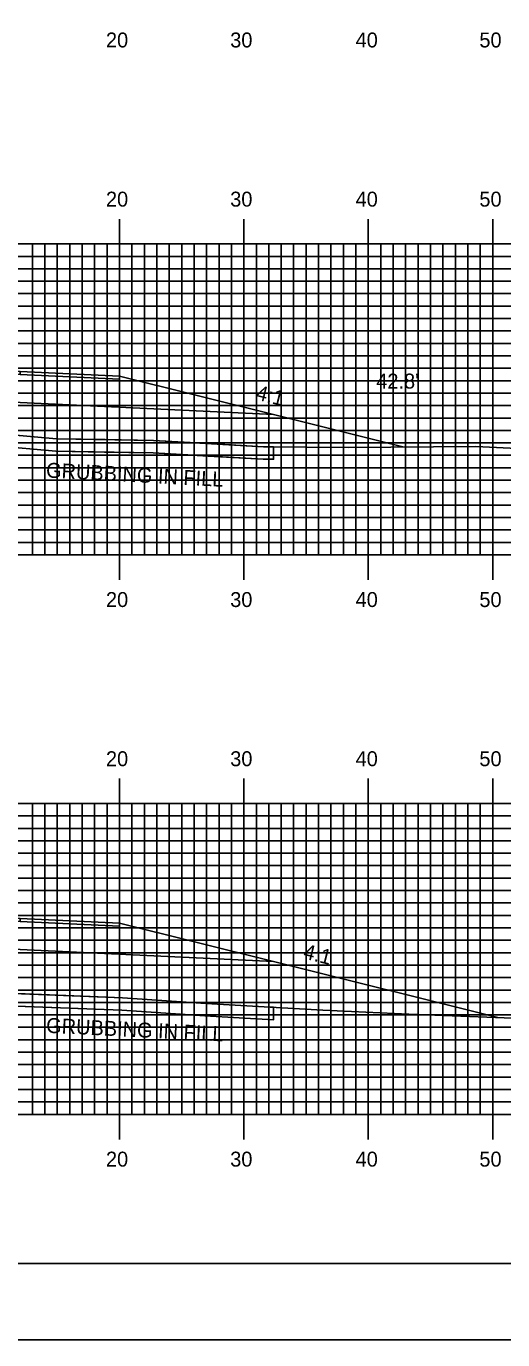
# Model space of a CAD drawing. Extents: x 1814128 to 1814471, y 442591 to 442811.
# Drawn here: x 1814306.5 to 1814344.8, y 442590.5 to 442696.2 of the extents above; entities that cross this region are included whole.
import ezdxf

# ---------------------------------------------------------------- set-up
doc = ezdxf.new("R2010")
doc.units = 0
for name, color, linetype in [('ANNOTATION', 7, 'Continuous'), ('BORDER', 7, 'Continuous'), ('D_Roadway_Centerline', 7, 'Continuous'), ('D_Roadway_Edge_Shoulder', 7, 'Continuous'), ('D_Roadway_SlopeLines', 7, 'Continuous'), ('D_Roadway_SubGrade', 7, 'Continuous'), ('D_Text_Standard', 7, 'Continuous'), ('GRUBBING IN FILL', 7, 'Continuous'), ('H_V ANNOTATION', 7, 'Continuous'), ('MAJOR', 7, 'Continuous'), ('MINOR', 7, 'Continuous'), ('PLOT BOUNDARY', 7, 'Continuous'), ('S_Roadway_Centerline', 7, 'Continuous')]:
    doc.layers.add(name, color=color, linetype=linetype)

msp = doc.modelspace()

# ---------------------------------------------------------------- linework, layer by layer
at = {"layer": 'BORDER'}
msp.add_lwpolyline([(1814144.39, 442596.67), (1814464.39, 442596.67), (1814464.39, 442806.67), (1814144.39, 442806.67)], close=True, dxfattribs=at)
at = {"layer": 'D_Roadway_Centerline'}
for points in [[(1814257.01, 442665.16), (1814261.99, 442666.41), (1814263.12, 442666.69), (1814273.99, 442669.41), (1814281.99, 442669.57), (1814293.99, 442668.99), (1814305.99, 442668.42), (1814313.99, 442668.03), (1814326.37, 442664.94), (1814336.78, 442662.34)], [(1814250.99, 442620.3), (1814259.24, 442622.37), (1814260.37, 442622.65), (1814271.24, 442625.37), (1814281.99, 442625.58), (1814293.99, 442625.01), (1814305.99, 442624.43), (1814313.99, 442624.05), (1814326.37, 442620.95), (1814344.4, 442616.45)]]:
    msp.add_lwpolyline(points, dxfattribs=at)
at = {"layer": 'D_Roadway_Edge_Shoulder'}
for points in [[(1814305.99, 442668.42), (1814313.99, 442668.03), (1814313.99, 442667.78), (1814305.99, 442668.17)], [(1814305.99, 442624.43), (1814313.99, 442624.05), (1814313.99, 442623.8), (1814305.99, 442624.18)]]:
    msp.add_lwpolyline(points, close=True, dxfattribs=at)
at = {"layer": 'D_Roadway_SlopeLines'}
for points in [[(1814313.99, 442668.03), (1814326.37, 442664.94), (1814336.78, 442662.34)], [(1814313.99, 442624.05), (1814326.37, 442620.95), (1814344.4, 442616.45)]]:
    msp.add_lwpolyline(points, dxfattribs=at)
at = {"layer": 'D_Roadway_SubGrade'}
for points in [[(1814281.99, 442667.07), (1814263.12, 442666.69), (1814273.99, 442669.41), (1814273.99, 442669.16), (1814281.99, 442669.32), (1814293.99, 442668.74), (1814305.99, 442668.17), (1814313.99, 442667.78), (1814313.99, 442668.03), (1814326.37, 442664.94), (1814305.99, 442665.92), (1814293.99, 442666.49)], [(1814281.99, 442623.08), (1814260.37, 442622.65), (1814271.24, 442625.37), (1814271.24, 442625.12), (1814281.99, 442625.33), (1814293.99, 442624.76), (1814305.99, 442624.18), (1814313.99, 442623.8), (1814313.99, 442624.05), (1814326.37, 442620.95), (1814305.99, 442621.93), (1814293.99, 442622.51)]]:
    msp.add_lwpolyline(points, close=True, dxfattribs=at)
at = {"layer": 'GRUBBING IN FILL'}
for p, q in [((1814326.37, 442662.35), (1814326.37, 442661.35)), ((1814326.37, 442662.35), (1814326.37, 442661.35)), ((1814326.37, 442617.28), (1814326.37, 442616.28)), ((1814326.37, 442617.28), (1814326.37, 442616.28))]:
    msp.add_line(p, q, dxfattribs=at)
for points in [[(1814263.12, 442663.84), (1814275.17, 442663.27), (1814283.53, 442662.9), (1814291.88, 442663.36), (1814299.24, 442662.87), (1814308.87, 442662), (1814316.69, 442661.86), (1814325.53, 442661.36), (1814326.37, 442661.35)], [(1814263.12, 442663.84), (1814275.17, 442663.27), (1814283.53, 442662.9), (1814291.88, 442663.36), (1814299.24, 442662.87), (1814308.87, 442662), (1814316.69, 442661.86), (1814325.53, 442661.36), (1814326.37, 442661.35)], [(1814260.37, 442618.87), (1814265.26, 442618.76), (1814273.92, 442618.48), (1814282.8, 442618.22), (1814297.25, 442617.7), (1814314.18, 442617.05), (1814320.86, 442616.6), (1814326.37, 442616.28)], [(1814260.37, 442618.87), (1814265.26, 442618.76), (1814273.92, 442618.48), (1814282.8, 442618.22), (1814297.25, 442617.7), (1814314.18, 442617.05), (1814320.86, 442616.6), (1814326.37, 442616.28)]]:
    msp.add_lwpolyline(points, dxfattribs=at)
for points in [[(1814293.99, 442664.22), (1814295.6, 442664.12), (1814299.32, 442663.86), (1814304.12, 442663.43), (1814308.93, 442663), (1814312.83, 442662.93), (1814316.73, 442662.86), (1814321.15, 442662.61), (1814325.57, 442662.36), (1814326.37, 442662.35), (1814326.37, 442661.35), (1814325.53, 442661.36), (1814321.11, 442661.61), (1814316.69, 442661.86), (1814312.78, 442661.93), (1814308.87, 442662), (1814304.05, 442662.43), (1814299.24, 442662.87), (1814293.99, 442663.22)], [(1814293.99, 442664.22), (1814295.6, 442664.12), (1814299.32, 442663.86), (1814304.12, 442663.43), (1814308.93, 442663), (1814312.83, 442662.93), (1814316.73, 442662.86), (1814321.15, 442662.61), (1814325.57, 442662.36), (1814326.37, 442662.35), (1814326.37, 442661.35), (1814325.53, 442661.36), (1814321.11, 442661.61), (1814316.69, 442661.86), (1814312.78, 442661.93), (1814308.87, 442662), (1814304.05, 442662.43), (1814299.24, 442662.87), (1814293.99, 442663.22)], [(1814293.99, 442618.82), (1814297.29, 442618.7), (1814305.76, 442618.38), (1814314.23, 442618.05), (1814320.92, 442617.59), (1814325.63, 442617.32), (1814326.37, 442617.28), (1814326.37, 442616.28), (1814323.61, 442616.44), (1814320.86, 442616.6), (1814314.18, 442617.05), (1814305.72, 442617.38), (1814297.25, 442617.7), (1814293.99, 442617.82)], [(1814293.99, 442618.82), (1814297.29, 442618.7), (1814305.76, 442618.38), (1814314.23, 442618.05), (1814320.92, 442617.59), (1814325.63, 442617.32), (1814326.37, 442617.28), (1814326.37, 442616.28), (1814323.61, 442616.44), (1814320.86, 442616.6), (1814314.18, 442617.05), (1814305.72, 442617.38), (1814297.25, 442617.7), (1814293.99, 442617.82)]]:
    msp.add_lwpolyline(points, close=True, dxfattribs=at)
at = {"layer": 'MAJOR'}
for p, q in [((1814313.99, 442680.67), (1814313.99, 442678.67)), ((1814323.99, 442680.67), (1814323.99, 442678.67)), ((1814333.99, 442680.67), (1814333.99, 442678.67)), ((1814343.99, 442680.67), (1814343.99, 442678.67)), ((1814153.99, 442678.67), (1814433.99, 442678.67)), ((1814153.99, 442678.67), (1814433.99, 442678.67)), ((1814313.99, 442653.67), (1814313.99, 442678.67)), ((1814323.99, 442653.67), (1814323.99, 442678.67)), ((1814333.99, 442653.67), (1814333.99, 442678.67)), ((1814343.99, 442653.67), (1814343.99, 442678.67)), ((1814153.99, 442673.67), (1814433.99, 442673.67)), ((1814153.99, 442668.67), (1814433.99, 442668.67)), ((1814153.99, 442663.67), (1814433.99, 442663.67)), ((1814153.99, 442658.67), (1814433.99, 442658.67)), ((1814153.99, 442653.67), (1814433.99, 442653.67)), ((1814153.99, 442653.67), (1814433.99, 442653.67)), ((1814313.99, 442651.66), (1814313.99, 442653.67)), ((1814323.99, 442651.66), (1814323.99, 442653.67)), ((1814333.99, 442651.66), (1814333.99, 442653.67)), ((1814343.99, 442651.66), (1814343.99, 442653.67)), ((1814313.99, 442635.67), (1814313.99, 442633.67)), ((1814323.99, 442635.67), (1814323.99, 442633.67)), ((1814333.99, 442635.67), (1814333.99, 442633.67)), ((1814343.99, 442635.67), (1814343.99, 442633.67)), ((1814153.99, 442633.67), (1814433.99, 442633.67)), ((1814153.99, 442633.67), (1814433.99, 442633.67)), ((1814313.99, 442608.67), (1814313.99, 442633.67)), ((1814323.99, 442608.67), (1814323.99, 442633.67)), ((1814333.99, 442608.67), (1814333.99, 442633.67)), ((1814343.99, 442608.67), (1814343.99, 442633.67)), ((1814153.99, 442628.67), (1814433.99, 442628.67)), ((1814153.99, 442623.67), (1814433.99, 442623.67)), ((1814153.99, 442618.67), (1814433.99, 442618.67)), ((1814153.99, 442613.67), (1814433.99, 442613.67)), ((1814153.99, 442608.67), (1814433.99, 442608.67)), ((1814153.99, 442608.67), (1814433.99, 442608.67)), ((1814313.99, 442606.66), (1814313.99, 442608.67)), ((1814323.99, 442606.66), (1814323.99, 442608.67)), ((1814333.99, 442606.66), (1814333.99, 442608.67)), ((1814343.99, 442606.66), (1814343.99, 442608.67))]:
    msp.add_line(p, q, dxfattribs=at)
at = {"layer": 'MINOR'}
for p, q in [((1814306.99, 442653.67), (1814306.99, 442678.67)), ((1814307.99, 442653.67), (1814307.99, 442678.67)), ((1814308.99, 442653.67), (1814308.99, 442678.67)), ((1814309.99, 442653.67), (1814309.99, 442678.67)), ((1814310.99, 442653.67), (1814310.99, 442678.67)), ((1814311.99, 442653.67), (1814311.99, 442678.67)), ((1814312.99, 442653.67), (1814312.99, 442678.67)), ((1814314.99, 442653.67), (1814314.99, 442678.67)), ((1814315.99, 442653.67), (1814315.99, 442678.67)), ((1814316.99, 442653.67), (1814316.99, 442678.67)), ((1814317.99, 442653.67), (1814317.99, 442678.67)), ((1814318.99, 442653.67), (1814318.99, 442678.67)), ((1814319.99, 442653.67), (1814319.99, 442678.67)), ((1814320.99, 442653.67), (1814320.99, 442678.67)), ((1814321.99, 442653.67), (1814321.99, 442678.67)), ((1814322.99, 442653.67), (1814322.99, 442678.67)), ((1814324.99, 442653.67), (1814324.99, 442678.67)), ((1814325.99, 442653.67), (1814325.99, 442678.67)), ((1814326.99, 442653.67), (1814326.99, 442678.67)), ((1814327.99, 442653.67), (1814327.99, 442678.67)), ((1814328.99, 442653.67), (1814328.99, 442678.67)), ((1814329.99, 442653.67), (1814329.99, 442678.67)), ((1814330.99, 442653.67), (1814330.99, 442678.67)), ((1814331.99, 442653.67), (1814331.99, 442678.67)), ((1814332.99, 442653.67), (1814332.99, 442678.67)), ((1814334.99, 442653.67), (1814334.99, 442678.67)), ((1814335.99, 442653.67), (1814335.99, 442678.67)), ((1814336.99, 442653.67), (1814336.99, 442678.67)), ((1814337.99, 442653.67), (1814337.99, 442678.67)), ((1814338.99, 442653.67), (1814338.99, 442678.67)), ((1814339.99, 442653.67), (1814339.99, 442678.67)), ((1814340.99, 442653.67), (1814340.99, 442678.67)), ((1814341.99, 442653.67), (1814341.99, 442678.67)), ((1814342.99, 442653.67), (1814342.99, 442678.67)), ((1814153.99, 442677.67), (1814433.99, 442677.67)), ((1814153.99, 442676.67), (1814433.99, 442676.67)), ((1814153.99, 442675.67), (1814433.99, 442675.67)), ((1814153.99, 442674.67), (1814433.99, 442674.67)), ((1814153.99, 442672.67), (1814433.99, 442672.67)), ((1814153.99, 442671.67), (1814433.99, 442671.67)), ((1814153.99, 442670.67), (1814433.99, 442670.67)), ((1814153.99, 442669.67), (1814433.99, 442669.67)), ((1814153.99, 442667.67), (1814433.99, 442667.67)), ((1814153.99, 442666.67), (1814433.99, 442666.67)), ((1814153.99, 442665.67), (1814433.99, 442665.67)), ((1814153.99, 442664.67), (1814433.99, 442664.67)), ((1814153.99, 442662.67), (1814433.99, 442662.67)), ((1814153.99, 442661.67), (1814433.99, 442661.67)), ((1814153.99, 442660.67), (1814433.99, 442660.67)), ((1814153.99, 442659.67), (1814433.99, 442659.67)), ((1814153.99, 442657.67), (1814433.99, 442657.67)), ((1814153.99, 442656.67), (1814433.99, 442656.67)), ((1814153.99, 442655.67), (1814433.99, 442655.67)), ((1814153.99, 442654.67), (1814433.99, 442654.67)), ((1814306.99, 442608.67), (1814306.99, 442633.67)), ((1814307.99, 442608.67), (1814307.99, 442633.67)), ((1814308.99, 442608.67), (1814308.99, 442633.67)), ((1814309.99, 442608.67), (1814309.99, 442633.67)), ((1814310.99, 442608.67), (1814310.99, 442633.67)), ((1814311.99, 442608.67), (1814311.99, 442633.67)), ((1814312.99, 442608.67), (1814312.99, 442633.67)), ((1814314.99, 442608.67), (1814314.99, 442633.67)), ((1814315.99, 442608.67), (1814315.99, 442633.67)), ((1814316.99, 442608.67), (1814316.99, 442633.67)), ((1814317.99, 442608.67), (1814317.99, 442633.67)), ((1814318.99, 442608.67), (1814318.99, 442633.67)), ((1814319.99, 442608.67), (1814319.99, 442633.67)), ((1814320.99, 442608.67), (1814320.99, 442633.67)), ((1814321.99, 442608.67), (1814321.99, 442633.67)), ((1814322.99, 442608.67), (1814322.99, 442633.67)), ((1814324.99, 442608.67), (1814324.99, 442633.67)), ((1814325.99, 442608.67), (1814325.99, 442633.67)), ((1814326.99, 442608.67), (1814326.99, 442633.67)), ((1814327.99, 442608.67), (1814327.99, 442633.67)), ((1814328.99, 442608.67), (1814328.99, 442633.67)), ((1814329.99, 442608.67), (1814329.99, 442633.67)), ((1814330.99, 442608.67), (1814330.99, 442633.67)), ((1814331.99, 442608.67), (1814331.99, 442633.67)), ((1814332.99, 442608.67), (1814332.99, 442633.67)), ((1814334.99, 442608.67), (1814334.99, 442633.67)), ((1814335.99, 442608.67), (1814335.99, 442633.67)), ((1814336.99, 442608.67), (1814336.99, 442633.67)), ((1814337.99, 442608.67), (1814337.99, 442633.67)), ((1814338.99, 442608.67), (1814338.99, 442633.67)), ((1814339.99, 442608.67), (1814339.99, 442633.67)), ((1814340.99, 442608.67), (1814340.99, 442633.67)), ((1814341.99, 442608.67), (1814341.99, 442633.67)), ((1814342.99, 442608.67), (1814342.99, 442633.67)), ((1814153.99, 442632.67), (1814433.99, 442632.67)), ((1814153.99, 442631.67), (1814433.99, 442631.67)), ((1814153.99, 442630.67), (1814433.99, 442630.67)), ((1814153.99, 442629.67), (1814433.99, 442629.67)), ((1814153.99, 442627.67), (1814433.99, 442627.67)), ((1814153.99, 442626.67), (1814433.99, 442626.67)), ((1814153.99, 442625.67), (1814433.99, 442625.67)), ((1814153.99, 442624.67), (1814433.99, 442624.67)), ((1814153.99, 442622.67), (1814433.99, 442622.67)), ((1814153.99, 442621.67), (1814433.99, 442621.67)), ((1814153.99, 442620.67), (1814433.99, 442620.67)), ((1814153.99, 442619.67), (1814433.99, 442619.67)), ((1814153.99, 442617.67), (1814433.99, 442617.67)), ((1814153.99, 442616.67), (1814433.99, 442616.67)), ((1814153.99, 442615.67), (1814433.99, 442615.67)), ((1814153.99, 442614.67), (1814433.99, 442614.67)), ((1814153.99, 442612.67), (1814433.99, 442612.67)), ((1814153.99, 442611.67), (1814433.99, 442611.67)), ((1814153.99, 442610.67), (1814433.99, 442610.67)), ((1814153.99, 442609.67), (1814433.99, 442609.67))]:
    msp.add_line(p, q, dxfattribs=at)
at = {"layer": 'PLOT BOUNDARY'}
msp.add_lwpolyline([(1814128.21, 442590.55), (1814468.21, 442590.55), (1814468.21, 442810.55), (1814128.21, 442810.55)], close=True, dxfattribs=at)
at = {"layer": 'S_Roadway_Centerline'}
for points in [[(1814153.99, 442667.97), (1814161.32, 442667.4), (1814167.95, 442667.05), (1814174.94, 442666.98), (1814184.48, 442667.03), (1814193.54, 442667.21), (1814201.48, 442666.94), (1814209.68, 442667.06), (1814217.54, 442666.63), (1814226.05, 442666.58), (1814234.88, 442666.16), (1814242.26, 442666.03), (1814250.37, 442665.6), (1814258.58, 442665.06), (1814275.22, 442664.27), (1814283.53, 442663.9), (1814291.88, 442664.37), (1814299.32, 442663.86), (1814308.93, 442663), (1814316.73, 442662.86), (1814325.57, 442662.36), (1814332.4, 442662.3), (1814342.63, 442662.38), (1814356.37, 442661.7)], [(1814153.99, 442623.21), (1814163.78, 442622.13), (1814167.6, 442621.98), (1814184.17, 442621.87), (1814189.15, 442621.88), (1814200.08, 442621.51), (1814209.56, 442620.94), (1814215.95, 442620.64), (1814226.91, 442620.8), (1814232.69, 442620.8), (1814239.23, 442620.49), (1814249.37, 442620.39), (1814258.43, 442619.91), (1814265.29, 442619.76), (1814273.95, 442619.48), (1814282.83, 442619.21), (1814297.29, 442618.7), (1814314.23, 442618.05), (1814320.92, 442617.59), (1814330.34, 442617.05), (1814337.24, 442616.72), (1814347.7, 442616.32)]]:
    msp.add_lwpolyline(points, dxfattribs=at)

# ---------------------------------------------------------------- texts
at = {"layer": 'ANNOTATION'}
for p in [(1814324.89, 442666.17), (1814328.7, 442621.23)]:
    msp.add_text('4:1', height=1.2, rotation=345.9638, dxfattribs=at).set_placement(p)
at = {"layer": 'D_Text_Standard'}
msp.add_text("42.8'", height=1.2, dxfattribs=at).set_placement((1814334.63, 442667.04))
at = {"layer": 'GRUBBING IN FILL'}
for rotation, p in [(356.9606, (1814308.06, 442659.89)), (357.1645, (1814308.07, 442615.24))]:
    msp.add_text('GRUBBING IN FILL', height=1.2, rotation=rotation, dxfattribs=at).set_placement(p)
at = {"layer": 'H_V ANNOTATION'}
for s, p in [('20', (1814312.9, 442694.47)), ('30', (1814322.89, 442694.47)), ('40', (1814332.97, 442694.47)), ('50', (1814342.92, 442694.47)), ('20', (1814312.9, 442681.67)), ('30', (1814322.89, 442681.67)), ('40', (1814332.97, 442681.67)), ('50', (1814342.92, 442681.67)), ('20', (1814312.9, 442649.47)), ('30', (1814322.89, 442649.47)), ('40', (1814332.97, 442649.47)), ('50', (1814342.92, 442649.47)), ('20', (1814312.9, 442636.67)), ('30', (1814322.89, 442636.67)), ('40', (1814332.97, 442636.67)), ('50', (1814342.92, 442636.67)), ('20', (1814312.9, 442604.47)), ('30', (1814322.89, 442604.47)), ('40', (1814332.97, 442604.47)), ('50', (1814342.92, 442604.47))]:
    msp.add_text(s, height=1.2, dxfattribs=at).set_placement(p)

doc.saveas('drawing.dxf')
